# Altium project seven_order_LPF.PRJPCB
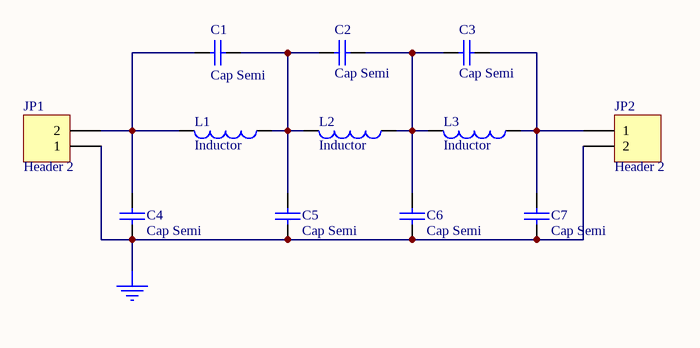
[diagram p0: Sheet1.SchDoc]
1 sheet, 12 parts. Net scope: global (net labels, ports and power ports of the same name join across sheets).
Board file: PCB.PCBDOC

## Sheet Sheet1.SchDoc
size B

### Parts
C1  Cap Semi  [C3216-1206]
C2  Cap Semi  [C3216-1206]
C3  Cap Semi  [C3216-1206]
C4  Cap Semi  [C3216-1206]
C5  Cap Semi  [C3216-1206]
C6  Cap Semi  [C3216-1206]
C7  Cap Semi  [C3216-1206]
JP1  Header 2  [HDR1X2]
JP2  Header 2  [HDR1X2]
L1  Inductor  [C1005-0402]
L2  Inductor  [C1005-0402]
L3  Inductor  [C1005-0402]

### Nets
GND: C4.2 C5.2 C6.2 C7.2 JP1.1 JP2.2
NetC1_1: C1.1 C4.1 JP1.2 L1.2
NetC1_2: C1.2 C2.1 C5.1 L1.1 L2.2
NetC2_2: C2.2 C3.1 C6.1 L2.1 L3.2
NetC3_2: C3.2 C7.1 JP2.1 L3.1

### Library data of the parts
C1-C7 = Cap Semi: Capacitor (Semiconductor SIM Model); Manufacturer: Generic Components; Class I: Passive; Value: 100pF
JP1 JP2 = Header 2: Header, 2-Pin; Manufacturer: Generic Components; Class I: Connector
L1-L3 = Inductor: Manufacturer: Generic Components; Class I: Passive; Value: 10mH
